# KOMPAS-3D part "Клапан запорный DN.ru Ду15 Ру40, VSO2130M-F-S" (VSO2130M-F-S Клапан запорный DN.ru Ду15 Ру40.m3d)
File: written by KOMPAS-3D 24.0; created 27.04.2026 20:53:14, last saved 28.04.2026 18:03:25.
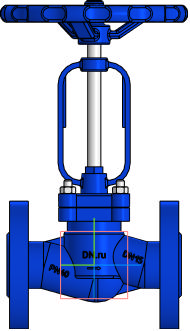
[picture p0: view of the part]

Document properties: Автор: DN.ru; Полное имя файла: C:\Работа\ГОТОВЫЕ ИСХОДНИКИ\VSO2130M-F-S Клапан запорный сальниковый DN.ru Ду15-100 Ру40\DN15\VSO2130M-F-S Клапан запорный DN.ru Ду15 Ру40.m3d

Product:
- Part/product: Клапан запорный DN.ru Ду15 Ру40  | designation VSO2130M-F-S
    Масса: 3.7
    Раздел спецификации: Прочие изделия
    Примечание: D090-01979

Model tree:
1. Операция без истории:1

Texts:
  VSO2130M-F-S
